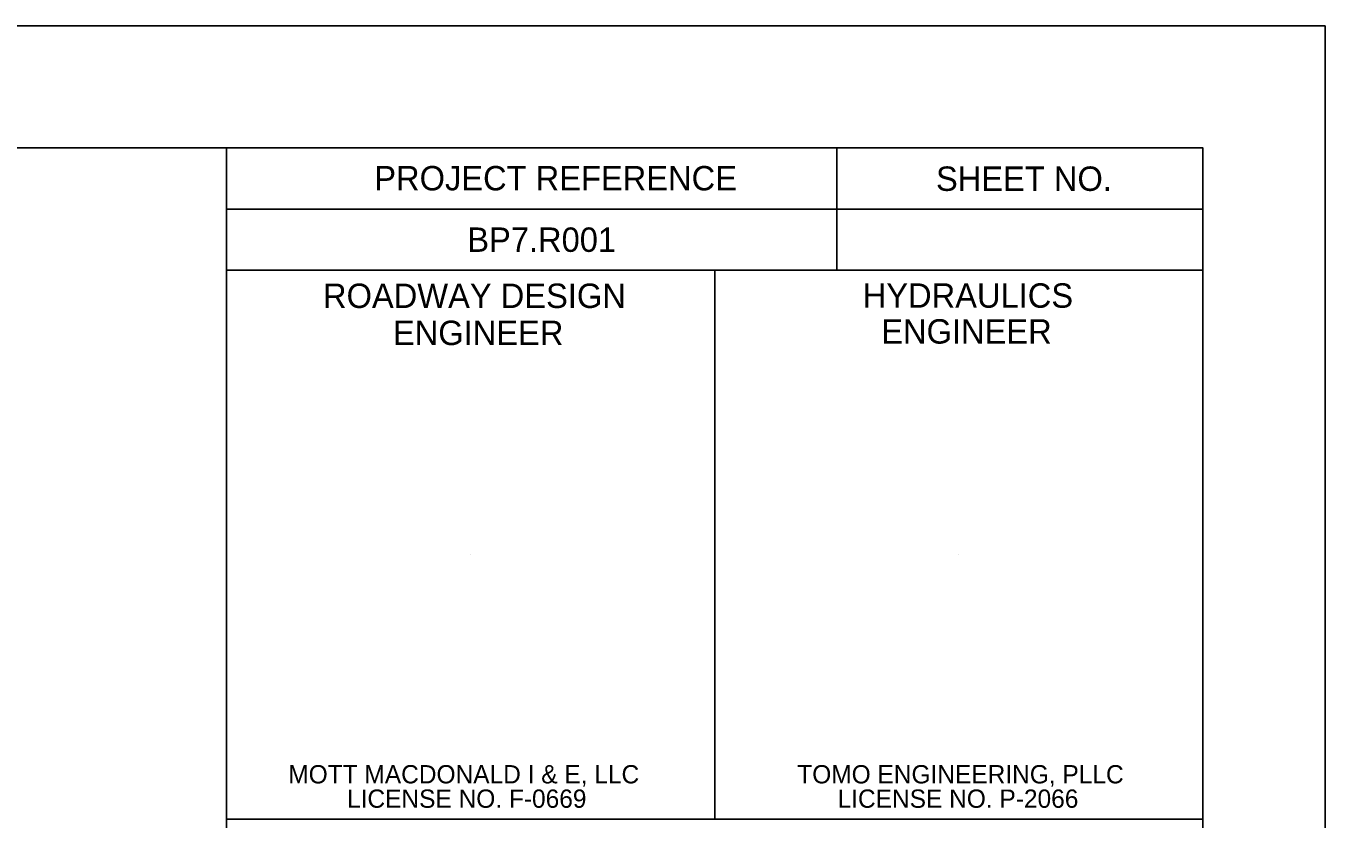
# Model space of a CAD drawing. Extents: x 2467493 to 2469404, y 649492 to 650592.
# Drawn here: x 2468926.4 to 2469192.5, y 650429.9 to 650592.5 of the extents above; entities that cross this region are included whole.
import ezdxf

# ---------------------------------------------------------------- set-up
doc = ezdxf.new("R2010")
doc.units = 0
for name, color, linetype in [('Old_Level_18', 7, 'Continuous'), ('Old_Level_2', 7, 'Continuous'), ('Old_Level_3', 7, 'Continuous'), ('Old_Level_40', 7, 'Continuous'), ('Old_Level_42', 7, 'Continuous'), ('Old_Level_44', 7, 'Continuous'), ('Old_Level_45', 7, 'Continuous'), ('Old_Level_62', 7, 'Continuous'), ('Old_Level_63', 7, 'Continuous'), ('Scratch_Level_3', 7, 'Continuous'), ('Sheet Sticker Exception Certification CELL', 7, 'Continuous')]:
    doc.layers.add(name, color=color, linetype=linetype)

msp = doc.modelspace()

# ---------------------------------------------------------------- linework, layer by layer
at = {"layer": 'Old_Level_18'}
msp.add_lwpolyline([(2469167.55, 650567.49), (2467667.55, 650567.49), (2467667.55, 649517.49), (2469167.55, 649517.49)], close=True, dxfattribs=at)
at = {"layer": 'Old_Level_40'}
for p, q in [((2469092.55, 650567.44), (2469092.55, 650542.44)), ((2468967.5, 650554.94), (2469167.55, 650554.94))]:
    msp.add_line(p, q, dxfattribs=at)
msp.add_lwpolyline([(2468967.5, 650567.49), (2469167.55, 650567.49), (2469167.55, 650542.44), (2468967.5, 650542.44)], close=True, dxfattribs=at)
at = {"layer": 'Old_Level_42'}
msp.add_line((2468967.5, 650542.44), (2469167.55, 650542.44), dxfattribs=at)
msp.add_line((2468967.5, 650542.44), (2469167.55, 650542.44), dxfattribs=at)
for points in [[(2468967.5, 650542.44), (2469067.55, 650542.44), (2469067.55, 650429.94), (2468967.5, 650429.94)], [(2469067.55, 650542.44), (2469167.55, 650542.44), (2469167.55, 650429.94), (2469067.55, 650429.94)]]:
    msp.add_lwpolyline(points, close=True, dxfattribs=at)
at = {"layer": 'Old_Level_62'}
msp.add_line((2469167.55, 650567.49), (2469167.55, 650567.49), dxfattribs=at)
msp.add_lwpolyline([(2467517.55, 649517.49), (2469167.55, 649517.49), (2469167.55, 650567.49), (2467517.55, 650567.49)], close=True, dxfattribs=at)
at = {"layer": 'Old_Level_63'}
msp.add_line((2469192.55, 650592.49), (2469192.55, 650592.49), dxfattribs=at)
msp.add_lwpolyline([(2467492.55, 649492.49), (2469192.55, 649492.49), (2469192.55, 650592.49), (2467492.55, 650592.49)], close=True, dxfattribs=at)
at = {"layer": 'Scratch_Level_3'}
for p, q in [((2469017.4, 650484.09), (2469017.4, 650484.09)), ((2469117.45, 650484.09), (2469117.45, 650484.09))]:
    msp.add_line(p, q, dxfattribs=at)
at = {"layer": 'Sheet Sticker Exception Certification CELL'}
for p, q in [((2468967.5, 650406.44), (2468967.5, 650429.94)), ((2468967.5, 650429.94), (2469167.54, 650429.94))]:
    msp.add_line(p, q, dxfattribs=at)

# ---------------------------------------------------------------- texts
at = {"layer": 'Old_Level_2'}
for s, height, p in [('ROADWAY DESIGN', 5.0001, (2468987.27, 650534.69)), ('ENGINEER', 5, (2469001.6, 650527.09))]:
    msp.add_text(s, height=height, dxfattribs=at).set_placement(p)
at = {"layer": 'Old_Level_3'}
for s, p in [('HYDRAULICS', (2469097.84, 650534.74)), ('ENGINEER', (2469101.63, 650527.39))]:
    msp.add_text(s, height=5, dxfattribs=at).set_placement(p)
for s, p in [('TOMO ENGINEERING, PLLC', (2469084.43, 650437.24)), ('LICENSE NO. P-2066', (2469092.69, 650432.24))]:
    msp.add_text(s, height=3.75, rotation=360, dxfattribs=at).set_placement(p)
at = {"layer": 'Old_Level_44'}
for s, height, p in [('PROJECT REFERENCE', 5.0001, (2468997.77, 650558.79)), ('SHEET NO.', 5, (2469112.85, 650558.69)), ('BP7.R001', 5, (2469016.83, 650546.19))]:
    msp.add_text(s, height=height, dxfattribs=at).set_placement(p)
at = {"layer": 'Old_Level_45'}
for s, p in [('MOTT MACDONALD I & E, LLC', (2468980.16, 650437.24)), (' LICENSE NO. F-0669', (2468990.8, 650432.24))]:
    msp.add_text(s, height=3.75, rotation=360, dxfattribs=at).set_placement(p)

doc.saveas('drawing.dxf')
